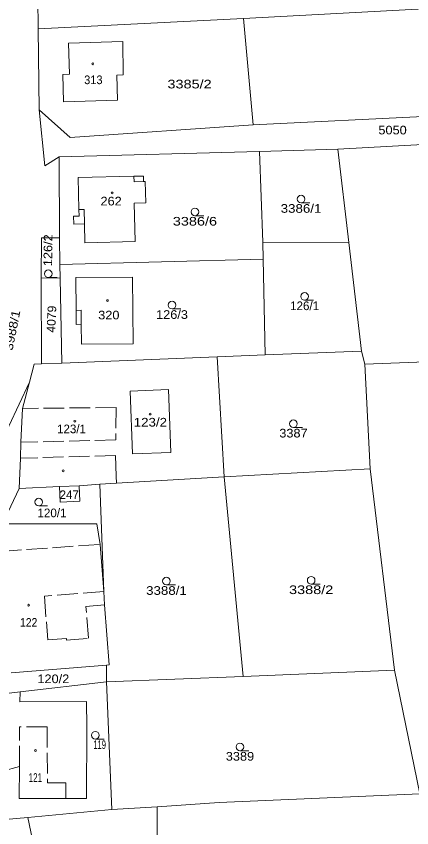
# Model space of a CAD drawing. Extents: x -590528 to -586543, y -1119609 to -1116685.
# Drawn here: x -588608.7 to -588531, y -1118281.3 to -1118121.8 of the extents above; entities that cross this region are included whole.
import ezdxf
from ezdxf.enums import TextEntityAlignment as Align

# ---------------------------------------------------------------- set-up
doc = ezdxf.new("R2010")
doc.units = 0
doc.header["$LTSCALE"] = 0.68
doc.linetypes.add('LONG_DASHED', pattern=[7.5, 6, -1.5])
for name, color, linetype, lineweight in [('1', 7, 'Continuous', 13), ('2', 7, 'LONG_DASHED', 13), ('3', 7, 'Continuous', 13), ('6', 7, 'Continuous', 13)]:
    doc.layers.add(name, color=color, linetype=linetype, lineweight=lineweight)

msp = doc.modelspace()

# ---------------------------------------------------------------- linework, layer by layer
at = {"layer": '1'}
for p, q in [((-588604.48, -1118116.1), (-588604.34, -1118124.26)), ((-588467.73, -1118117.14), (-588564.01, -1118122.22)), ((-588604.34, -1118124.26), (-588564.01, -1118122.22)), ((-588564.01, -1118122.22), (-588562.14, -1118143.12)), ((-588604.14, -1118140.16), (-588604.34, -1118124.26)), ((-588562.14, -1118143.12), (-588445.35, -1118137.46)), ((-588562.14, -1118143.12), (-588598.04, -1118145.6)), ((-588600.24, -1118149.41), (-588560.9, -1118148.37)), ((-588560.9, -1118148.37), (-588545.5, -1118147.9)), ((-588560.9, -1118148.37), (-588560.21, -1118166.24)), ((-588545.5, -1118147.9), (-588543.34, -1118166.3)), ((-588603.05, -1118151.17), (-588600.24, -1118149.41)), ((-588600.16, -1118165.37), (-588600.24, -1118149.41)), ((-588585.55, -1118153.26), (-588596.5, -1118153.49)), ((-588583.65, -1118153.21), (-588585.55, -1118153.26)), ((-588583.63, -1118154.31), (-588583.65, -1118153.21)), ((-588596.5, -1118153.49), (-588596.34, -1118159.79)), ((-588583.63, -1118154.31), (-588583.33, -1118154.31)), ((-588583.33, -1118154.31), (-588583.22, -1118158.5)), ((-588583.22, -1118158.5), (-588585.47, -1118158.56)), ((-588585.47, -1118158.56), (-588585.28, -1118166.06)), ((-588597.41, -1118161.11), (-588596.31, -1118161.09)), ((-588597.37, -1118162.66), (-588597.41, -1118161.11)), ((-588596.31, -1118161.09), (-588596.34, -1118159.79)), ((-588595.27, -1118162.61), (-588597.37, -1118162.66)), ((-588595.27, -1118162.61), (-588595.18, -1118166.31)), ((-588603.7, -1118165.37), (-588603.77, -1118173.22)), ((-588595.18, -1118166.31), (-588585.28, -1118166.06)), ((-588560.21, -1118166.24), (-588543.34, -1118166.3)), ((-588560.13, -1118169.57), (-588560.21, -1118166.24)), ((-588540.83, -1118187.61), (-588543.34, -1118166.3)), ((-588600.07, -1118170.59), (-588560.13, -1118169.57)), ((-588600.07, -1118170.59), (-588600.02, -1118173.29)), ((-588560.13, -1118169.57), (-588559.75, -1118188.37)), ((-588600.02, -1118173.29), (-588603.77, -1118173.22)), ((-588603.77, -1118173.22), (-588603.72, -1118190.14)), ((-588600.02, -1118173.29), (-588599.72, -1118189.98)), ((-588596.95, -1118173.14), (-588585.8, -1118173.12)), ((-588596.95, -1118173.14), (-588596.92, -1118179.62)), ((-588585.8, -1118173.12), (-588585.67, -1118186.21)), ((-588596.9, -1118182.38), (-588596.92, -1118179.62)), ((-588595.9, -1118182.36), (-588596.9, -1118182.38)), ((-588595.84, -1118186.25), (-588595.9, -1118182.36)), ((-588595.84, -1118186.25), (-588585.67, -1118186.21)), ((-588569.17, -1118188.75), (-588559.75, -1118188.37)), ((-588559.75, -1118188.37), (-588540.83, -1118187.61)), ((-588603.72, -1118190.14), (-588599.72, -1118189.98)), ((-588599.72, -1118189.98), (-588569.17, -1118188.75)), ((-588567.83, -1118212.38), (-588569.17, -1118188.75)), ((-588606.07, -1118193.71), (-588605.13, -1118190.2)), ((-588605.13, -1118190.2), (-588603.72, -1118190.14)), ((-588540.17, -1118190.18), (-588539.16, -1118210.75)), ((-588625.37, -1118234.33), (-588606.07, -1118193.71)), ((-588607.46, -1118198.9), (-588606.07, -1118193.71)), ((-588586.31, -1118195.51), (-588578.76, -1118195.17)), ((-588586.31, -1118195.51), (-588585.79, -1118207.85)), ((-588578.76, -1118195.17), (-588578.32, -1118207.58)), ((-588578.32, -1118207.58), (-588585.79, -1118207.85)), ((-588567.83, -1118212.38), (-588539.16, -1118210.75)), ((-588539.16, -1118210.75), (-588534.32, -1118250.35)), ((-588588.97, -1118213.58), (-588567.83, -1118212.38)), ((-588596.31, -1118214.09), (-588592.26, -1118213.77)), ((-588592.26, -1118213.77), (-588588.97, -1118213.58)), ((-588592.26, -1118213.77), (-588591.47, -1118234.89)), ((-588608.08, -1118214.62), (-588611.39, -1118221.57)), ((-588600.05, -1118217.31), (-588600.19, -1118214.26)), ((-588596.31, -1118214.09), (-588596.18, -1118217.14)), ((-588596.18, -1118217.14), (-588600.05, -1118217.31)), ((-588592.82, -1118221.58), (-588611.39, -1118221.57)), ((-588592.18, -1118225.62), (-588592.82, -1118221.58)), ((-588592.18, -1118225.62), (-588591.47, -1118234.89)), ((-588591.47, -1118234.89), (-588591.34, -1118237.53)), ((-588591.34, -1118237.53), (-588590.42, -1118249.31)), ((-588590.93, -1118249.35), (-588590.96, -1118252.63)), ((-588534.32, -1118250.35), (-588529.35, -1118274.66)), ((-588590.96, -1118252.63), (-588564.05, -1118251.6)), ((-588590.96, -1118252.63), (-588607.9, -1118254.61)), ((-588590.96, -1118252.63), (-588589.88, -1118277.78)), ((-588607.93, -1118256.58), (-588607.9, -1118254.61)), ((-588607.93, -1118256.58), (-588594.84, -1118256.53)), ((-588594.79, -1118261.55), (-588594.84, -1118256.53)), ((-588594.79, -1118261.55), (-588594.89, -1118275.6)), ((-588611.39, -1118270.2), (-588608.03, -1118269.31)), ((-588608.07, -1118275.58), (-588608.03, -1118269.31)), ((-588529.35, -1118274.66), (-588568.79, -1118276.37)), ((-588580.97, -1118277.25), (-588581.01, -1118289.34)), ((-588580.97, -1118277.25), (-588568.79, -1118276.37)), ((-588606.41, -1118279.31), (-588601.67, -1118301.43))]:
    msp.add_line(p, q, dxfattribs=at)
msp.add_lwpolyline([(-588598.4, -1118127.08), (-588587.73, -1118126.76), (-588587.63, -1118133.31), (-588588.92, -1118133.4), (-588588.76, -1118138.31), (-588599.35, -1118138.64), (-588599.51, -1118133.23), (-588598.21, -1118133.19)], close=True, dxfattribs=at)
for points in [[(-588598.04, -1118145.6), (-588604.14, -1118140.16), (-588603.05, -1118151.17)], [(-588442.78, -1118145.68), (-588452.37, -1118142.81), (-588545.5, -1118147.9)], [(-588603.7, -1118165.37), (-588600.16, -1118165.37), (-588600.07, -1118170.59)], [(-588540.83, -1118187.61), (-588540.17, -1118190.18), (-588512.93, -1118189.15)], [(-588608.08, -1118214.62), (-588607.85, -1118208.69), (-588607.73, -1118205.55), (-588607.46, -1118198.9)], [(-588567.83, -1118212.38), (-588564.05, -1118251.6), (-588534.32, -1118250.35)], [(-588596.31, -1118214.09), (-588600.19, -1118214.26), (-588608.08, -1118214.62)], [(-588590.42, -1118249.31), (-588590.93, -1118249.35), (-588609.65, -1118250.91)], [(-588607.9, -1118254.61), (-588611.15, -1118255), (-588613.43, -1118255.27)], [(-588594.89, -1118275.6), (-588598.93, -1118275.59), (-588608.07, -1118275.58)], [(-588611.53, -1118279.79), (-588606.41, -1118279.31), (-588589.88, -1118277.78), (-588580.97, -1118277.25)]]:
    msp.add_lwpolyline(points, dxfattribs=at)
at = {"layer": '2'}
for p, q in [((-588585.55, -1118153.26), (-588585.52, -1118154.36)), ((-588585.52, -1118154.36), (-588583.63, -1118154.31)), ((-588596.34, -1118159.79), (-588595.34, -1118159.76)), ((-588595.34, -1118159.76), (-588595.27, -1118162.61)), ((-588595.92, -1118179.61), (-588596.92, -1118179.62)), ((-588595.9, -1118182.36), (-588595.92, -1118179.61)), ((-588589.02, -1118198.72), (-588607.46, -1118198.9)), ((-588589.02, -1118198.72), (-588589.11, -1118205.1)), ((-588589.11, -1118205.1), (-588607.73, -1118205.55)), ((-588589.15, -1118208.13), (-588607.85, -1118208.69)), ((-588611.7, -1118227.01), (-588592.18, -1118225.62)), ((-588591.47, -1118234.89), (-588603.13, -1118235.79)), ((-588594.98, -1118237.81), (-588591.34, -1118237.53)), ((-588594.49, -1118244.09), (-588594.98, -1118237.81)), ((-588598.8, -1118244.13), (-588598.78, -1118244.43)), ((-588598.78, -1118244.43), (-588594.49, -1118244.09)), ((-588608.03, -1118269.31), (-588607.99, -1118261.47)), ((-588602.59, -1118261.5), (-588607.99, -1118261.47)), ((-588602.59, -1118261.5), (-588602.54, -1118272.53)), ((-588598.94, -1118272.51), (-588602.54, -1118272.53)), ((-588598.93, -1118275.59), (-588598.94, -1118272.51))]:
    msp.add_line(p, q, dxfattribs=at)
for points in [[(-588589.15, -1118208.13), (-588589.01, -1118212.24), (-588588.97, -1118213.58)], [(-588603.13, -1118235.79), (-588602.47, -1118244.41), (-588598.8, -1118244.13)]]:
    msp.add_lwpolyline(points, dxfattribs=at)
at = {"layer": '6'}
for p, q in [((-588552.71, -1118158.48), (-588550.96, -1118158.48)), ((-588573.56, -1118161), (-588571.81, -1118161)), ((-588602.37, -1118173.16), (-588600.62, -1118173.16)), ((-588552.01, -1118177.62), (-588550.26, -1118177.62)), ((-588578.06, -1118179.34), (-588576.31, -1118179.34)), ((-588554.2, -1118202.66), (-588552.45, -1118202.66)), ((-588604.24, -1118218.06), (-588602.49, -1118218.06)), ((-588579.15, -1118233.6), (-588577.4, -1118233.6)), ((-588550.72, -1118233.45), (-588548.97, -1118233.45)), ((-588593.12, -1118263.91), (-588591.37, -1118263.91)), ((-588564.71, -1118266.2), (-588562.96, -1118266.2))]:
    msp.add_line(p, q, dxfattribs=at)
for centre, radius in [((-588593.6402, -1118131.1404), 0.175), ((-588589.8102, -1118156.5304), 0.175), ((-588552.71, -1118157.73), 0.75), ((-588573.56, -1118160.25), 0.75), ((-588602.37, -1118172.41), 0.75), ((-588552.01, -1118176.87), 0.75), ((-588590.7502, -1118177.6904), 0.175), ((-588578.06, -1118178.59), 0.75), ((-588597.1402, -1118201.4304), 0.175), ((-588582.3602, -1118200.0104), 0.175), ((-588554.2, -1118201.91), 0.75), ((-588599.4402, -1118211.1704), 0.175), ((-588604.24, -1118217.31), 0.75), ((-588579.15, -1118232.85), 0.75), ((-588550.72, -1118232.7), 0.75), ((-588606.2202, -1118237.5704), 0.175), ((-588593.12, -1118263.16), 0.75), ((-588564.71, -1118265.45), 0.75), ((-588604.9002, -1118266.1604), 0.175)]:
    msp.add_circle(centre, radius, dxfattribs=at)

# ---------------------------------------------------------------- texts
at = {"layer": '3'}
for s, width, p in [('313', 0.95, (-588593.51, -1118135.14)), ('3385/2', 1.25, (-588574.6105, -1118135.98)), ('262', 1.1, (-588590.02, -1118158.99)), ('3386/1', 1.15, (-588552.71, -1118160.43)), ('3386/6', 1.25, (-588573.56, -1118162.95)), ('320', 1.1, (-588590.4705, -1118181.39)), ('126/3', 1.1, (-588578.0605, -1118181.29)), ('123/2', 1.15, (-588582.31, -1118202.46)), ('3387', 1.1, (-588554.2, -1118204.61)), ('3388/1', 1.15, (-588579.1505, -1118235.55)), ('3388/2', 1.25, (-588550.7205, -1118235.4)), ('122', 0.9, (-588606.22, -1118241.82)), ('120/2', 1.1, (-588601.37, -1118252.91)), ('119', 0.65, (-588592.27, -1118265.86)), ('3389', 1.1, (-588564.71, -1118268.15)), ('121', 0.7, (-588604.9005, -1118272.32))]:
    msp.add_text(s, height=1.7, dxfattribs=dict(at, width=width)).set_placement(p, align=Align.CENTER)
at = {"layer": '3', "width": 1.1}
msp.add_text('5050', height=1.7, dxfattribs=at).set_placement((-588537.513, -1118145.02))
at = {"layer": '3'}
for s, rotation, width, p in [('126/2', 89.267, 1.1, (-588601.5805, -1118167.8084)), ('4079', 87.433, 1.05, (-588600.8985, -1118181.3821)), ('3988/1', 78.839, 1.15, (-588608.6178, -1118183.686))]:
    msp.add_text(s, height=1.7, rotation=rotation, dxfattribs=dict(at, width=width)).set_placement(p, align=Align.CENTER)
for s, p in [('126/1', (-588552.0105, -1118179.57)), ('123/1', (-588597.8005, -1118203.78)), ('247', (-588598.2515, -1118216.72)), ('120/1', (-588601.641, -1118220.29))]:
    msp.add_text(s, height=1.7, dxfattribs=at).set_placement(p, align=Align.CENTER)

doc.saveas('drawing.dxf')
